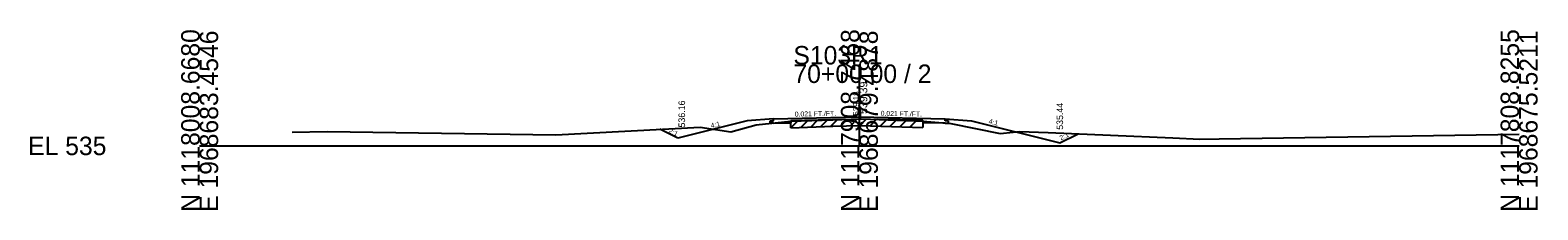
# Model space of a CAD drawing. Extents: x -26 to 203, y -10 to 12018.
# Drawn here: x -25.7 to 202.8, y 8990.3 to 9017.5 of the extents above; entities that cross this region are included whole.
import ezdxf

# ---------------------------------------------------------------- set-up
doc = ezdxf.new("R2010")
doc.units = 0
for name, color, linetype in [('Level 10', 7, 'Continuous'), ('Level 11', 7, 'Continuous'), ('Level 12', 7, 'Continuous'), ('Level 32', 7, 'Continuous'), ('Level 33', 7, 'Continuous'), ('Level 53', 7, 'Continuous'), ('Level 59', 7, 'Continuous'), ('Level 6', 7, 'Continuous'), ('Level 60', 7, 'Continuous'), ('Level 61', 7, 'Continuous'), ('Level 63', 7, 'Continuous'), ('Level 7', 7, 'Continuous')]:
    doc.layers.add(name, color=color, linetype=linetype)

msp = doc.modelspace()

# ---------------------------------------------------------------- linework, layer by layer
at = {"layer": 'Level 11'}
for p, q in [((86.5, 9003.8), (87, 9003.81)), ((86.5, 9003.44), (86.5, 9003.8)), ((87, 9003.45), (86.5, 9003.44)), ((87, 9003.81), (87, 9004.12)), ((113, 9003.81), (113, 9004.12)), ((113.5, 9003.8), (113, 9003.81)), ((113, 9003.45), (113.5, 9003.44)), ((113.5, 9003.44), (113.5, 9003.8))]:
    msp.add_line(p, q, dxfattribs=at)
at = {"layer": 'Level 12'}
for p, q in [((87, 9003.45), (89.63, 9003.5)), ((89.63, 9003.74), (89.63, 9003.5)), ((109.61, 9003.77), (109.61, 9003.52)), ((113, 9003.45), (109.61, 9003.52))]:
    msp.add_line(p, q, dxfattribs=at)
at = {"layer": 'Level 53'}
for p, q in [((89.63, 9003.86), (97.87, 9004.03)), ((89.63, 9003.74), (89.63, 9003.86)), ((109.61, 9003.88), (102.78, 9004.02)), ((109.61, 9003.77), (109.61, 9003.88))]:
    msp.add_line(p, q, dxfattribs=at)
at = {"layer": 'Level 59'}
for p, q in [((87, 9004.12), (100, 9004.39)), ((100, 9004.39), (113, 9004.12))]:
    msp.add_line(p, q, dxfattribs=at)
at = {"layer": 'Level 6'}
for p, q in [((87, 9004.12), (83, 9003.79)), ((113, 9004.12), (117, 9003.79))]:
    msp.add_line(p, q, dxfattribs=at)
at = {"layer": 'Level 60'}
for p, q in [((14.03, 9002.09), (19.35, 9002.16)), ((19.35, 9002.16), (53.98, 9001.68)), ((53.98, 9001.68), (75.86, 9002.84)), ((75.86, 9002.84), (80.51, 9002.13)), ((80.51, 9002.13), (84.34, 9003.21)), ((84.34, 9003.21), (89.63, 9003.74)), ((89.63, 9003.74), (95.97, 9003.97)), ((95.97, 9003.97), (100.14, 9004.11)), ((100.14, 9004.11), (101.66, 9004.06)), ((101.66, 9004.06), (109.61, 9003.77)), ((109.61, 9003.77), (113.87, 9003.39)), ((113.87, 9003.39), (121.36, 9001.89)), ((121.36, 9001.89), (123.33, 9002.1)), ((123.33, 9002.1), (124.26, 9002.2)), ((124.26, 9002.2), (128.6, 9002.02)), ((128.6, 9002.02), (147.49, 9001.22)), ((147.49, 9001.22), (151.62, 9001.04)), ((151.62, 9001.04), (154.55, 9001.08)), ((154.55, 9001.08), (200, 9001.77))]:
    msp.add_line(p, q, dxfattribs=at)
at = {"layer": 'Level 61'}
for p, q in [((89.63, 9002.74), (90.67, 9003.78)), ((89.63, 9002.74), (89.63, 9003.74)), ((89.63, 9002.74), (95.97, 9002.97)), ((91.13, 9002.79), (92.17, 9003.83)), ((92.63, 9002.85), (93.67, 9003.88)), ((94.13, 9002.9), (95.17, 9003.94)), ((95.63, 9002.95), (96.67, 9003.99)), ((95.97, 9002.97), (100.14, 9003.11)), ((97.13, 9003.01), (98.17, 9004.04)), ((98.63, 9003.06), (99.67, 9004.1)), ((100.13, 9003.11), (101.1, 9004.08)), ((100.14, 9003.11), (101.66, 9003.06)), ((101.63, 9003.06), (102.6, 9004.03)), ((101.66, 9003.06), (109.61, 9002.77)), ((103.13, 9003.01), (104.1, 9003.97)), ((104.63, 9002.95), (105.6, 9003.92)), ((106.13, 9002.9), (107.1, 9003.86)), ((107.63, 9002.84), (108.6, 9003.81)), ((109.61, 9003.77), (109.61, 9002.77))]:
    msp.add_line(p, q, dxfattribs=at)
at = {"layer": 'Level 63'}
for p, q in [((100, 9000), (100, 9012.34)), ((0, 9000), (100, 9000)), ((100, 9000), (200, 9000))]:
    msp.add_line(p, q, dxfattribs=at)
at = {"layer": 'Level 7'}
for p, q in [((72.49, 9001.16), (69.77, 9002.52)), ((83, 9003.79), (72.49, 9001.16)), ((117, 9003.79), (130.38, 9000.44)), ((130.38, 9000.44), (133.15, 9001.82))]:
    msp.add_line(p, q, dxfattribs=at)

# ---------------------------------------------------------------- texts
at = {"layer": 'Level 10'}
msp.add_text(' 539.18', height=0.9, rotation=90, dxfattribs=at).set_placement((99.95, 9004.25))
at = {"layer": 'Level 32'}
for s, rotation, p in [('0.021 FT./FT.', 1.1916, (90.21, 9004.44)), ('0.021 FT./FT.', 358.8084, (103.22, 9004.57)), ('2:1', 333.4349, (71, 9002.06)), ('4:1', 14.0362, (77.57, 9002.67)), ('4:1', 345.9638, (119.55, 9003.41)), ('2:1', 26.5651, (130.56, 9000.81))]:
    msp.add_text(s, height=0.75, rotation=rotation, dxfattribs=at).set_placement(p)
at = {"layer": 'Level 33'}
for s, p in [('536.16', (73.58, 9002.79)), ('535.44', (130.88, 9002.44))]:
    msp.add_text(s, height=1, rotation=90, dxfattribs=at).set_placement(p)
at = {"layer": 'Level 59'}
msp.add_text(' 539.39', height=1.2, rotation=90, dxfattribs=at).set_placement((101.2, 9004.39))
at = {"layer": 'Level 63'}
for s, p in [('N 1118008.6680', (0, 8990)), ('E 1968683.4546', (2.8, 8990)), ('N 1117908.7468', (100, 8990)), ('E 1968679.4878', (102.8, 8990)), ('N 1117808.8255', (200, 8990)), ('E 1968675.5211', (202.8, 8990))]:
    msp.add_text(s, height=2.8, rotation=90, dxfattribs=at).set_placement(p)
for s, p in [('S103R1', (90, 9012.34)), ('70+00.00 / 2', (90, 9009.54)), ('EL 535', (-26, 8998.6))]:
    msp.add_text(s, height=2.8, dxfattribs=at).set_placement(p)

doc.saveas('drawing.dxf')
